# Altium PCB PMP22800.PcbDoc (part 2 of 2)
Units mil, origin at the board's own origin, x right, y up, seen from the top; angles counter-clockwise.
Board outline 4251.97 x 3450 mil, 2 copper layers (Top Layer, Bottom Layer), stack 62 mil thick; 97 components, 47 nets, 286 pads, 121 vias.
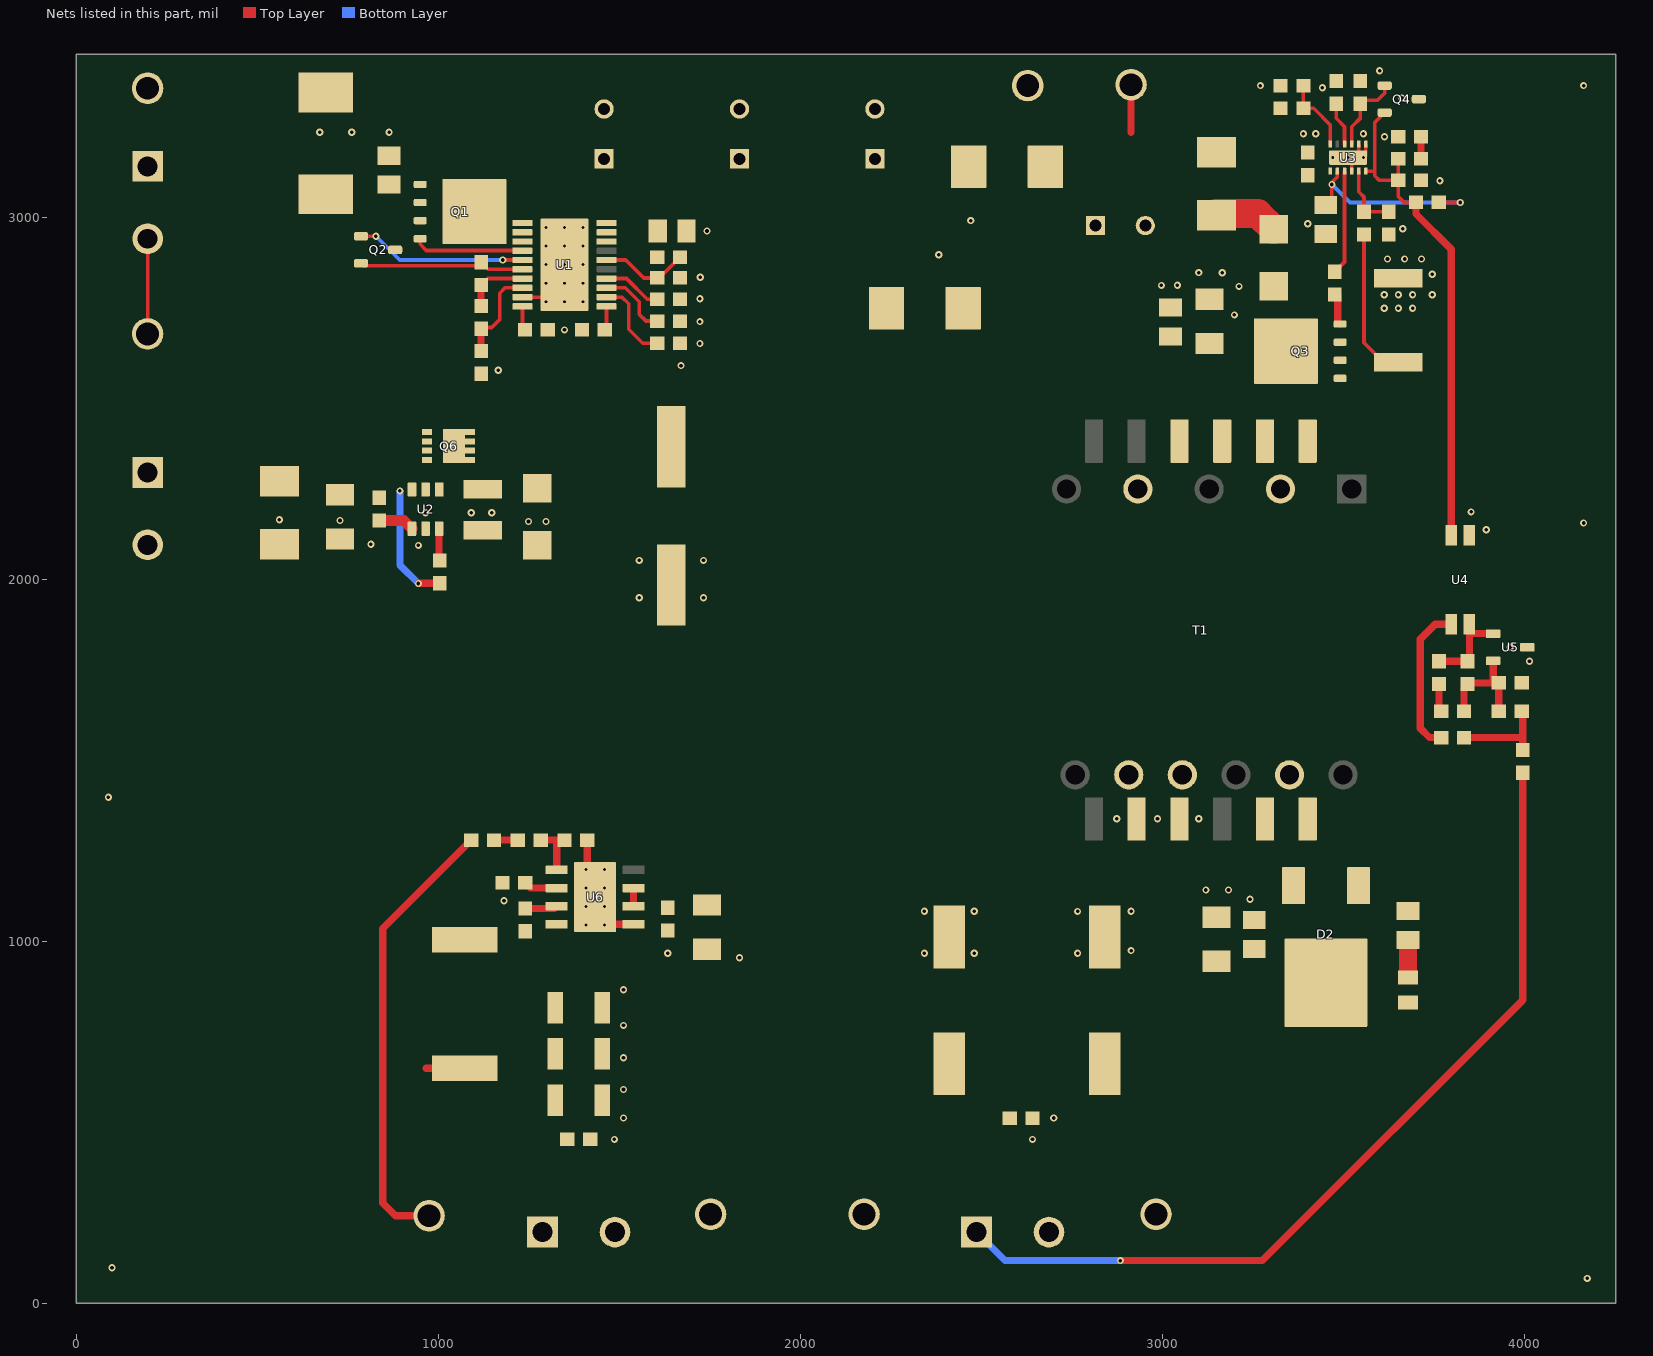
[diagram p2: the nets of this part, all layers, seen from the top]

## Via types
v1: diameter 20, hole 10, Top Layer to Bottom Layer, 91 vias
v2: diameter 19.68, hole 7.87, Top Layer to Bottom Layer, 16 vias
v3: diameter 19.68, hole 7.87, Top Layer to Bottom Layer, tented both sides, 10 vias
v4: diameter 20, hole 10, Top Layer to Bottom Layer, tented top, 4 vias

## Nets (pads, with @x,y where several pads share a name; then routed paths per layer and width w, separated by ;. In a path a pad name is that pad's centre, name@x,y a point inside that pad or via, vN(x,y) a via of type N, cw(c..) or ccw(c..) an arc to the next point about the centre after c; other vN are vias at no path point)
COMP: C22.1 C23.1 Q4.2 R14.2 U3.6 U4.4 | length 1400.3
  Top Layer w10: U3.6@3562.1,3127.27 3586.02,3127.27 ; Q4.2@3613.87,3288.88 3586.71,3261.72 3586.71,3127.27 ; C22.1@3651.28,3161.72 C23.1@3651.28,3102.66 ; R14.2@3700.49,3040.88 3667.86,3040.88 3651.28,3057.46 C23.1@3651.28,3102.66 ; 3586.02,3127.27 3586.71,3127.27 ; 3586.02,3127.27 3586.71,3126.58 ; 3586.71,3126.58 3586.71,3127.27 ; 3586.71,3126.58 3586.71,3114.37 3598.42,3102.66 C23.1@3651.28,3102.66
  Top Layer w20: R14.2@3700.49,3040.88 3700.49,3009.05 3798.03,2911.51 U4.4@3798.03,2122.05
IN_SYS: C5.1 D1.2 J1.2 Q1.1 Q1.2 Q1.3 Q2.2 R2.2 TP1.1 U1.6 | length 737.8
  Top Layer w10: J1.2@187.01,2930.76 J1.2@196.85,2940.61 TP1.1@196.85,2677.86 ; Q2.2@786.12,2872.7 792.95,2865.88 1108.27,2865.88 R2.2@1118.11,2875.72 1137.6,2856.23 U1.6@1232.28,2856.23
NetC1_1: C1.1 C2.1 C3.1 C4.1 J4.1 R1.2 U1.18 U1.19 U1.20
NetC6_1: C6.1 U1.10 | length 67.9
  Top Layer w10: U1.10@1232.28,2753.87 1232.28,2695.81 C6.1@1239.26,2688.83
NetC7_1: C7.1 R9.1 | length 95.3
  Top Layer w50: R9.1@3678.15,908.05 C7.1@3678.15,1003.31
NetC7_2: C7.2 D2.1 D2.3 pad.10 T1.11 T1.12
NetC18_1: C18.1 R17.1 R18.1 R21.2 U5.2 | length 307.5
  Top Layer w20: R18.1@3832.87,1634.84 3832.87,1700.79 C18.1@3842.72,1710.63 3845.67,1713.58 R21.2@3913.58,1713.58 ; U5.2@3913.58,1774.61 R21.2@3913.58,1713.58 ; R17.1@3929.33,1634.84 R21.2@3929.33,1713.58 R21.2@3913.58,1713.58
NetC18_2: C18.2 C20.2 U4.2 U5.1 | length 253.1
  Top Layer w20: C20.2@3763.98,1773.62 C18.2@3842.72,1773.62 3848.03,1778.94 U4.2@3848.03,1860.63 ; U4.2@3848.03,1875.98 U4.2@3848.03,1860.63 ; U5.1@3913.58,1850.39 3858.27,1850.39 U4.2@3848.03,1860.63
NetC19_2: C19.2 R15.1 U3.5 | length 194.8
  Top Layer w10: U3.5@3542.42,3127.27 3542.42,3070.11 3556.79,3055.74 R15.1@3556.79,3015.19 C19.2@3633.56,3015.19
NetC20_1: C20.1 R18.2 | length 78.2
  Top Layer w20: C20.1@3763.98,1710.63 3763.98,1640.75 R18.2@3769.88,1634.84
NetC22_2: C22.2 R22.2 | length 60.9
  Top Layer w20: C22.2@3714.27,3161.72 R22.2@3714.27,3222.6
NetC24_1: C24.1 U6.7 | length 89.3
  Top Layer w20: C24.1@1240.16,1090.55 1320.28,1090.55 U6.7@1326.77,1097.05
NetC24_2: C24.2 L1.1 U6.8
NetC27_1: C27.1 C28.1 C29.1 C30.2 J3.1 L1.2 R23.2 TP7.1 | length 1352.6
  Top Layer w20: 966.54,649.61 L1.2@1072.83,649.61 ; TP7.1@974.41,241.84 881.55,241.84 846.46,276.93 846.46,1035.24 R23.2@1090.75,1279.53
NetC31_1: C31.1 U6.6 | length 92.6
  Top Layer w20: C31.1@1240.16,1161.42 1254.53,1147.05 U6.6@1326.77,1147.05
NetC32_1: C32.1 C33.1 D6.1 J5.1 Q6.5 Q6.6 Q6.7 Q6.8 Q6.9 U2.4
NetC34_1: C34.1 C36.1 D7.2 J6.1 Q6.1 Q6.2 Q6.3 R27.2 U2.6 | length 337.1
  Top Layer w20: v1(944.88,1988.19) 945.87,1989.17 R27.2@1004.43,1989.17
  Bottom Layer w20: v1(893.7,2244.09) 893.7,2039.37 v1(944.88,1988.19)
NetC36_2: C36.2 U2.1 | length 99.9
  Top Layer w30: C36.2@836.61,2162.4 904.53,2162.4 U2.1@927.17,2139.76
NetD3_1: D3.1 D4.1 | length 177
  Top Layer w80: D3.1@3148.03,3009.86 3263.7,3009.86 D4.1@3307.09,2966.47
NetD4_2: D4.2 pad.2@3325.88,2249.19 Q3.5 Q3.6 Q3.7 Q3.8 Q3.9@3341.14,2629.92 T1.1 T1.2
NetQ1_4: Q1.4 Q2.3 U1.4 | length 305.8
  Top Layer w10: Q1.4@949.8,2940.61 949.8,2925.13 966.65,2908.28 1232.28,2908.28 U1.4@1232.28,2907.41
NetQ1_5: Q1.5 Q1.6 Q1.7 Q1.8 Q1.9@1099.41,3015.61 U1.1 U1.2 U1.3
NetQ2_1: Q2.1 U1.5 | length 473.4
  Top Layer w10: Q2.1@786.12,2947.51 v1(827.51,2947.51) ; v1(1177.95,2881.82) U1.5@1232.28,2881.82
  Bottom Layer w10: v1(827.51,2947.51) 893.19,2881.82 v1(1177.95,2881.82)
NetQ3_1: Q3.1 Q3.2 Q3.3 R15.2 R19.2 | length 416.7
  Top Layer w10: R15.2@3556.79,2952.2 3556.79,2652.94 R19.2@3610.58,2599.15
  Top Layer w20: R19.2@3610.58,2599.15 R19.2@3651.92,2599.15
NetQ3_4: Q3.4 R13.2 | length 84.1
  Top Layer w20: R13.2@3484.25,2786.35 3484.25,2711.42 Q3.4@3490.75,2704.92
NetQ6_4: Q6.4 U2.5
NetR1_1: R1.1 R3.2 U1.16 | length 247.4
  Top Layer w10: U1.16@1464.57,2881.82 1517.78,2881.82 1567.29,2832.32 R3.2@1604.59,2832.32 1610.04,2832.32 R1.1@1667.58,2889.86
NetR2_1: R2.1 R4.2 U1.7 | length 175.7
  Top Layer w10: R2.1@1118.11,2812.73 1136.02,2830.64 U1.7@1232.28,2830.64
  Top Layer w20: R4.2@1118.11,2758.6 R2.1@1118.11,2812.73
NetR4_1: R4.1 R7.2 U1.8 | length 257.1
  Top Layer w10: R4.1@1118.11,2695.6 1147.44,2695.6 1169.29,2717.46 1169.29,2790 1184.35,2805.05 U1.8@1232.28,2805.05
  Top Layer w20: R7.2@1118.11,2640.48 R4.1@1118.11,2695.6
NetR5_1: R5.1 U1.14 | length 163.8
  Top Layer w10: U1.14@1464.57,2830.64 1519.75,2830.64 1577.13,2773.26 R5.1@1604.59,2773.26
NetR6_1: R6.1 U1.11 | length 67
  Top Layer w10: R6.1@1459.74,2688.83 1464.57,2693.67 U1.11@1464.57,2753.87
NetR8_2: R8.2 U1.12 | length 233.7
  Top Layer w10: U1.12@1464.57,2779.46 1506.96,2779.46 1525.59,2760.83 1525.59,2690.95 1564.46,2652.08 R8.2@1604.59,2652.08
NetR10_1: R10.1 R11.2 U3.12 | length 209.1
  Top Layer w10: R11.2@3389.46,3363.68 R10.1@3389.46,3300.69 3418.01,3300.69 3463.68,3255.02 U3.12@3463.68,3202.07
NetR12_1: R12.1 R16.2 R17.2 | length 271.6
  Top Layer w20: R16.2@3833.07,1562.65 3990.69,1562.65 3995.28,1558.07 ; R17.2@3992.32,1634.84 3995.28,1631.89 3995.28,1558.07 ; R12.1@3995.28,1528.54 3995.28,1558.07
NetR13_1: R13.1 U3.3 | length 289.2
  Top Layer w10: R13.1@3475.92,2849.34 3503.05,2876.47 U3.3@3503.05,3127.27
NetR16_1: R16.1 U4.1 | length 417.9
  Top Layer w20: R16.1@3770.08,1562.65 3737.74,1562.65 3712.01,1588.39 3712.01,1834.25 3753.74,1875.98 U4.1@3798.03,1875.98
NetR20_2: R20.2 U3.10 | length 121
  Top Layer w10: R20.2@3479.79,3313.49 3479.79,3273.43 3503.05,3250.17 U3.10@3503.05,3202.07
NetR23_1: R23.1 R24.1 | length 65.7
  Top Layer w20: R23.1@1153.74,1279.53 R24.1@1219.49,1279.53
NetR24_2: R24.2 R25.2 U6.5 | length 126.8
  Top Layer w20: R24.2@1282.48,1279.53 1326.77,1279.53 U6.5@1326.77,1197.05
NetR26_2: R26.2 U1.13 | length 198.5
  Top Layer w10: U1.13@1464.57,2805.05 1516.51,2805.05 1555.12,2766.44 1555.12,2731.57 1573.39,2713.3 R26.2@1604.59,2713.3
NetR27_1: R27.1 U2.3 | length 88.6
  Top Layer w20: U2.3@1001.97,2139.76 1001.97,2054.63 R27.1@1004.43,2052.17
PGND: C1.2 C2.2 C3.2 C4.2 C5.2 C6.2 C8.2 C11.2 C12.2 C13.2 C17.1 C19.1 C21.2 C23.2 C32.2 C33.2 C34.2 D1.1 D6.2 D7.1 J1.1 J6.2 Q4.3 R3.1 R5.2 R6.2 R7.1 R8.1 R11.1 R19.1 R20.1 R22.1 R26.1 TP2.1 TP5.1 U1.9 U1.21 U2.2 U3.4 U3.7 U3.8 U3.13 U4.3 | length 245.9
  Top Layer w10: U1.9@1232.28,2779.46 1335.63,2779.46 v3(1348.43,2766.67) ; v2(3512.89,3164.67) 3522.73,3154.83 U3.4@3522.73,3127.27 ; U3.8@3542.42,3202.07 3542.42,3177.46 v2(3555.21,3164.67) 3562.1,3171.56 U3.7@3562.1,3202.07
  other v1: 1555.08,1948.82 1732.28,1948.82 1555.08,2052.17 1732.28,2052.17 944.88,2093.5 813.68,2097.05 3894.43,2136.81 4163.39,2155.51 1249.11,2159.45 1297.24,2159.45 728.35,2162.4 561.02,2164.37 964.57,2184.06 1090.84,2184.06 1147.44,2184.06 3852.56,2186.02 1165.39,2577.49 1670.08,2590.29 1722.44,2651.36 1722.44,2711.67 3198.82,2730.26 3612.55,2748.75 3651.92,2748.75 3690.94,2748.75 1722.44,2774.87 3612.55,2786.15 3651.92,2786.22 3690.94,2786.15 3745.22,2786.15 3211.6,2808.99 2997.28,2811.66 3041.34,2812.26 1723.25,2833.93 3745.22,2842.26 3100.39,2847.2 3165.33,2846.92 3621.75,2884.65 3668.99,2884.65 2381.89,2896.62 1742.13,2962.05 3401.38,2982.28 2470.47,2990.78 3766.43,3100.76 3389.46,3230.81 3423.38,3230.81 3555.21,3230.81 672.05,3234.64 761.01,3234.64 863.88,3234.64 3661.12,3329.24 3441.93,3357.78 3270.72,3363.68 4163.39,3363.68 3599.96,3404.97
  other v2: 1297.24,2817.85 1348.43,2817.85 1399.61,2817.85 1297.24,2869.03 1348.43,2869.03 1399.61,2869.03 1297.24,2920.21 1348.43,2920.21 1399.61,2920.21 3470.57,3164.67
  other v3: 1297.24,2766.67 1399.61,2766.67 1297.24,2971.39 1348.43,2971.39 1399.61,2971.39
  other v4: 1348.43,2688.83 3715.7,2884.65 3664.07,2967.95 3613.28,3222.6
SGND: C9.2 C10.2 C14.2 C15.2 C16.2 C25.2 C26.2 C27.2 C28.2 C29.2 C30.1 C31.2 J2.2 J3.2 pad.7 pad.8 R21.1 R25.1 T1.8 T1.9 TP6.1 TP8.1 U5.3 U6.1 U6.9 | length 163.8
  Top Layer w20: v3(1407.48,1198.82) 1411.42,1202.76 R25.1@1411.42,1279.53 ; v3(1458.66,1045.28) 1460.43,1047.05 U6.1@1539.37,1047.05
  other v1: 4173.23,68.9 98.43,98.43 1486.22,452.76 2641.17,452.76 1511.33,511.81 2699.67,511.81 1511.33,590.55 1511.33,678.15 1511.33,767.72 1511.33,866.14 1831.78,954.72 1633.86,967.32 2342.52,966.83 2480.32,967.32 2765.75,966.83 2913.39,974.41 2342.52,1083.31 2480.32,1083.31 2765.75,1082.68 2913.39,1083.31 1181.43,1112.2 3242,1116.14 3120.08,1141.73 3182.4,1141.73 2986.36,1338.19 2874.02,1338.58 3100.39,1338.58 88.58,1397.64 4013.98,1773.62 3960.83,1812.01
  other v2: 1407.48,1096.46 1458.66,1096.46 1407.48,1147.64 1458.66,1147.64
  other v3: 1407.48,1045.28 1458.66,1198.82
SS: C21.1 Q4.1 U3.9 | length 221.1
  Top Layer w10: U3.9@3522.73,3202.07 3522.73,3249.9 3546.94,3274.12 C21.1@3546.94,3313.49 3556.79,3323.33 3593.86,3323.33 3613.87,3343.35 Q4.1@3613.87,3363.68
VCC: C17.2 R14.1 U3.2 | length 549.6
  Top Layer w10: C17.2@3451.25,3033.54 C17.2@3468.2,3033.54 ; C17.2@3468.2,3034.86 v1(3468.2,3090.55) 3468.2,3096.91 3483.36,3112.07 U3.2@3483.36,3127.27 ; R14.1@3763.48,3040.88 v1(3822.53,3040.88)
  Bottom Layer w10: v1(3468.2,3090.55) 3517.88,3040.88 v1(3822.53,3040.88)
VIN_PRI: C8.1 C11.1 C12.1 C13.1 D3.2 J4.2 J5.2 pad.4 R10.2 T1.3 T1.4 TP3.1 U3.1 | length 131.5
  Top Layer w20: 2913.39,3234.64 TP3.1@2913.39,3366.14
VOUT_24V: C9.1 C10.1 C14.1 C15.1 C16.1 C25.1 C26.1 D2.2 J2.1 R9.2 R12.2 TP4.1 U6.2 U6.3 | length 2517.3
  Top Layer w20: U6.2@1539.37,1097.05 U6.3@1539.37,1147.05 ; v1(2883.86,118.11) 3275.87,118.11 3995.28,837.51 R12.2@3995.28,1465.55
  Bottom Layer w20: J2.1@2486.61,196.85 2565.35,118.11 v1(2883.86,118.11)
pads on no net: Q1.9@1044.88,2958.52 Q1.9@1044.88,3015.61 Q1.9@1044.88,3072.69 Q1.9@1081.49,3015.61 Q1.9@1114.96,2958.52 Q1.9@1114.96,3015.61 Q1.9@1114.96,3072.69 Q3.9@3325.59,2572.83 Q3.9@3325.59,2629.92 Q3.9@3325.59,2687.01 Q3.9@3359.05,2629.92 Q3.9@3395.67,2572.83 Q3.9@3395.67,2629.92 Q3.9@3395.67,2687.01 T1.5 T1.6 T1.7 T1.10 U1.15 U1.17 U3.11 U6.4

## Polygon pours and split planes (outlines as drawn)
VOUT_24V on Top Layer "TOP_LAYER_VOUT_24V_P004" (solid, remove dead copper, pour order 4): 2248.71,1023.62 2366.82,905.51 2883.12,905.51 3001.23,1023.62 3225.13,1023.62 3572.83,1023.62 3598.82,997.64 3598.82,879.53 3612.2,866.14 3710.63,866.14 3730.31,846.46 3730.31,748.03 3520.6,538.31 2608.27,538.31 2608.27,110.76 2556.57,59.06 2234.25,59.06 2007.87,285.43 2007.87,828.46 1770.58,1065.75 1515.75,1065.75 1505.91,1075.59 1505.91,1112.2 1574.8,1112.2 1620.67,1158.07 1909.45,1158.07 2114.26,1158.07
SGND on Top Layer "TOP_LAYER_SGND_P044" (solid, remove dead copper, pour order 44): 4226.48,1834.25 3186.07,1834.25 2808.51,1456.69 49.21,1456.69 19.68,1427.17 19.68,78.74 68.9,29.53 4202.76,29.53 4226.48,53.25
PGND on Top Layer "TOP_LAYER_PGND_P040" (solid, remove dead copper, pour order 40): 25.49,1874.12 49.21,1850.39 1978.35,1850.39 2225,2097.05 4199.31,2097.05 4232.28,2130.02 4232.28,3385.83 4192.91,3425.2 45.17,3425.2 25.49,3405.51
NetC27_1 on Top Layer "TOP_LAYER_NETC27_1_P036" (solid, remove dead copper, pour order 36): 1368.11,872.05 1120.08,872.05 895.67,647.64 895.67,529.53 895.67,45.9 912.04,29.53 1371.06,29.53 1387.8,46.26 1387.8,852.36
NetC7_2 on Top Layer "TOP_LAYER_NETC7_2_P034" (solid, remove dead copper, pour order 34): 3228.35,1397.64 3228.35,1518.87 3264.6,1555.12 3388,1555.12 3415.23,1527.89 3415.23,1437.01 3730.31,1121.92 3730.31,1061.61 3712.01,1043.31 3364.17,1043.31 3228.35,1179.13
NetQ3_1 on Top Layer "TOP_LAYER_NETQ3_1_P030" (solid, remove dead copper, pour order 30): 3513.78,2785.43
NetQ3_1 on Top Layer "TOP_LAYER_NETQ3_1_P002" (solid, remove dead copper, pour order 2): 3475.92,2673.95 3464.57,2662.6 3464.57,2542.13 3479.13,2527.56 3704.52,2527.56 3733.04,2556.08 3733.04,2619.02 3678.11,2673.95
NetD4_2 on Top Layer "TOP_LAYER_NETD4_2_P028" (solid, remove dead copper, pour order 28): 3238.19,2324.24 3238.19,2217.32 3271.46,2184.06 3411.75,2184.06 3441.93,2214.24 3441.93,2730.26 3378.41,2792.85 3378.41,2846.92 3356.3,2869.03 3257.87,2869.03 3238.19,2849.34
VIN_PRI on Top Layer "TOP_LAYER_VIN_PRI_P000" (solid, remove dead copper, pour order 0): 3465.24,3149.9 3380.31,3149.9 3360.92,3169.29 3361.46,3169.83 3361.46,3317.71 3351.78,3327.39 3283.64,3327.39 3243.65,3287.4 2687.01,3287.4 2605.98,3206.37 2605.98,3071.04 2497.54,2962.6 2353.46,2818.52 2353.46,2670.78 2455.35,2568.9 2741.93,2568.9 2841.05,2469.78 2841.05,2227.85 2884.84,2184.06 3115.01,2184.06 3200.79,2269.83 3200.79,2673.95 3169.82,2704.92 2993.9,2704.92 2913.39,2785.43 2913.39,3026.94 2957.49,3071.04 3358.64,3071.04 3425.2,3071.04 3474.96,3120.8 3474.96,3131.2 3470.52,3135.64 3470.56,3144.58
NetC24_2 on Top Layer "TOP_LAYER_NETC24_2_P026" (solid, remove dead copper, pour order 26): 1362.2,1062.99 976.38,1062.99 966.54,1053.15 966.54,962.6 974.41,954.72 1171.26,954.72 1214.57,998.03 1269.68,998.03 1301.18,1029.53 1361.22,1029.53 1368.11,1036.42 1368.11,1057.09
NetC32_1 on Top Layer "TOP_LAYER_NETC32_1_P008" (solid, remove dead copper, pour order 8): 1781.5,2208.76 1889.01,2208.76 2335.99,2655.75 2335.99,2827.33 2321.89,2841.43 2122.93,2841.43 1781.5,2500 1055.3,2500 990.93,2435.63 990.93,2222.27 1004.43,2208.76
NetQ6_4 on Top Layer "TOP_LAYER_NETQ6_4_P024" (solid, remove dead copper, pour order 24): 949.6,2227.9 981.1,2227.9 981.1,2342.52 949.6,2342.52
NetC34_1 on Top Layer "TOP_LAYER_NETC34_1_P022" (solid, remove dead copper, pour order 22): 20.67,2213.58 20.67,2451.77 34.18,2465.28 982.84,2465.28 997.34,2450.79 997.34,2342.52 941.73,2342.52 941.73,2228.35 907.28,2193.9 40.35,2193.9
NetC1_1 on Top Layer "TOP_LAYER_NETC1_1_P006" (solid, remove dead copper, pour order 6): 2519.68,3021.65 2551.97,3021.65 2588.58,3058.27 2588.58,3197.75 2551.69,3238.19 2401.57,3238.19 1440.56,3238.19 1417.32,3214.95 1417.32,2941.21 1434.43,2924.11 1518.29,2924.11 1578.23,2864.17 1633.86,2864.17 1633.86,2994.16 1661.35,3021.65
NetQ1_4 on Top Layer "TOP_LAYER_NETQ1_4_P020" (solid, remove dead copper, pour order 20): 972.44,2952.76 882.58,2952.76 853.05,2923.23 853.05,2890.42 860.93,2882.55 961.31,2882.55 975.89,2897.13 975.89,2949.31
NetQ1_5 on Top Layer "TOP_LAYER_NETQ1_5_P012" (solid, remove dead copper, pour order 12): 1011.81,3129.92 997.34,3115.45 997.34,2938.36 1013.78,2921.91 1268.37,2921.91 1269.68,2923.23 1269.68,3120.08 1259.84,3129.92
IN_SYS on Top Layer "TOP_LAYER_IN_SYS_P010" (solid, remove dead copper, pour order 10): 167.32,2830.64 80.04,2830.64 62.72,2847.96 62.72,3045 73.64,3055.92 255.91,3055.92 329.9,3129.92 334.65,3129.92 969.15,3129.92 984.25,3114.82 984.25,2986.02 967.39,2969.16 764.43,2969.16 748.03,2952.76 748.03,2910.1 761.01,2897.13 803.66,2897.13 825.33,2875.46 823.88,2874.02 823.88,2849.34 805.18,2830.64 787.4,2830.64
SGND on Bottom Layer "BOTTOM_LAYER_SGND_P042" (solid, remove dead copper, pour order 42): 4232.28,1834.25 3185.76,1834.25 2808.2,1456.69 49.21,1456.69 19.68,1427.17 19.68,78.74 68.9,29.53 4202.76,29.53 4232.28,59.06
PGND on Bottom Layer "BOTTOM_LAYER_PGND_P038" (solid, remove dead copper, pour order 38): 25.49,1874.12 49.21,1850.39 1978.35,1850.39 2225,2097.05 4198.43,2097.05 4232.28,2130.91 4232.28,3385.83 4192.91,3425.2 45.17,3425.2 25.49,3405.51

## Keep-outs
Keep-Out Layer:
  text ".Layer_Name" at 577,-858.49 h60

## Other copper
Top Layer:
  text ".Layer_Name" at 577,-858.49 h60
Bottom Layer:
  text ".Layer_Name" at 577,-858.49 h60

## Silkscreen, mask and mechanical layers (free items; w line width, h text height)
Top Overlay:
  text "'.PRJ_Number'.PCB_Rev" at 167.32,59.06 h108.27
  text ".Layer_Name" at 577,-858.49 h60
Bottom Overlay:
  text ".Layer_Name" at 577,-858.49 h60
Top Paste:
  text ".Layer_Name" at 577,-858.49 h60
Bottom Paste:
  text ".Layer_Name" at 577,-858.49 h60
Top Solder:
  text ".Layer_Name" at 577,-858.49 h60
  text ".Layer_Name" at 577,-858.49 h60
Bottom Solder:
  text ".Layer_Name" at 577,-858.49 h60
Drill Guide:
  text ".Layer_Name" at 577,-858.49 h60
M1 Board Outline:
  the board outline again, w10
  text ".Layer_Name" at 577,-858.49 h60
M2 Board Dimensions:
  rectangle: 0,-275 125,-150
  rectangle: 125,-400 500,-275
  lines w7: 0,-275 1000,-275 ; 125,-400 125,-150 ; 250,-400 250,-150 ; 500,-400 500,-150 ; 750,-400 750,-150 ; 0,-400 1000,-400 1000,-150 0,-150 0,-400
  text ".Layer_Name" at 577,-858.49 h60
M3 3D STEP Top:
  text ".Layer_Name" at 577,-858.49 h60
M4 3D STEP Bottom:
  text ".Layer_Name" at 577,-858.49 h60
M5 Assembly Top:
  lines w10: -292,-930.17 6308,-930.17 ; -292,-726.83 6310,-726.83 ; -292,-523.5 -292,-1133.5 3713,-1133.5 6310,-1133.5 6310,-523.5 -291.5,-523.5 -291.5,-1133.5 1284,-1133.5 ; 2173,-1133.5 2173,-523.5 ; 3440,-726.83 3440,-523.5 ; 4280,-726.83 4280,-523.5 ; 4902,-1140 4902,-937.17
  text "COMPONENTS MARKED 'DNP' SHOULD NOT BE POPULATED." at 1153.5,-318.5 h60
  text "ASSEMBLY VARIANT:" at 1153,-434 h60
  text ".VariantName" at 2189,-434 h60
  text "PCB VIEWED FROM TOP SIDE" at -228.5,-655.67 h60
  text "BOARD #:" at 2248,-655.67 h60
  text ".PRJ_Number" at 2793.5,-655.67 h60
  text "REV:" at 3638,-655.67 h60
  text ".PCB_Rev" at 3929.5,-655.67 h60
  text "SVN REV:" at 4476,-655.67 h60
  text ".VersionControl_RevNumber" at 4982,-655.67 h60
  text "TID #:" at 2248,-859 h60
  text ".TID" at 2793.5,-859 h60
  text "PLOT NAME =" at -228.5,-1064.34 h60
  text ".plot_File_Name" at 577,-1064.34 h60
  text "GENERATED    :" at 2250,-1064.34 h60
  text ".Print_Date" at 3119.5,-1064.34 h60
  text ".Print_Time" at 3848.5,-1064.34 h60
  text "TEXAS INSTRUMENTS" at 5113,-1064.34 h60
M6 Assembly Bottom:
  lines w10: -292.5,-727.33 6309.5,-727.33 ; -290.5,-930.67 6309.5,-930.67 ; 1115.5,-1140.5 1115.5,-937.67 ; 1737.5,-727.33 1737.5,-524 ; 2577.5,-727.33 2577.5,-524 ; 3844.5,-1134 3844.5,-524 ; 4733.5,-1134 6309,-1134 6309,-524 -292.5,-524 -292.5,-1134 2304.5,-1134 6309.5,-1134 6309.5,-524
  text "COMPONENTS MARKED 'DNP' SHOULD NOT BE POPULATED." at 6102,-318 h60
  text ".VariantName" at 5058,-434 h60
  text "ASSEMBLY VARIANT:" at 6097,-434 h60
  text ".VersionControl_RevNumber" at 1035.5,-656.17 h60
  text "SVN REV:" at 1541.5,-656.17 h60
  text ".PCB_Rev" at 2088,-656.17 h60
  text "REV:" at 2379.5,-656.17 h60
  text ".PRJ_Number" at 3224,-656.17 h60
  text "BOARD #:" at 3769.5,-656.17 h60
  text "PCB VIEWED FROM BOTTOM SIDE" at 6246,-656.17 h60
  text ".TID" at 3224,-859.5 h60
  text "TID #:" at 3769.5,-859.5 h60
  text "TEXAS INSTRUMENTS" at 904.5,-1064.84 h60
  text ".Print_Time" at 2169,-1064.84 h60
  text ".Print_Date" at 2898,-1064.84 h60
  text "GENERATED    :" at 3767.5,-1064.84 h60
  text ".plot_File_Name" at 5440.5,-1064.84 h60
  text "PLOT NAME =" at 6246,-1064.84 h60
M9 Title Sheet:
  drawing of 57 lines, arcs and shapes, not listed
  text "1" at 739.84,8036.5 h70
  text "2" at 3235.5,8036.5 h70
  text "3" at 5724.84,8036.5 h70
  text "4" at 8231.51,8036.5 h70
  text "5" at 10730.5,8036.5 h70
  text "6" at 13235.5,8036.5 h70
  text "A" at -416.5,6893.5 h70
  text "A" at 14383.5,6893.5 h70
  text "B" at -416.5,4513.5 h70
  text "B" at 14383.5,4513.5 h70
  text "C" at -416.5,2138.5 h70
  text "C" at 14383.5,2138.5 h70
  text "PROJECT TITLE:" at 11343.5,277.5 h45
  text ".PRJ_Title" at 11393.5,144.17 h70
  text "DESIGNED FOR:" at 11343.5,-23.5 h45
  text ".PRJ_Customer" at 11393.5,-163.5 h70
  text "D" at -416.5,-231.5 h70
  text "D" at 14383.5,-231.5 h70
  text "FILE NAME:" at 11343.5,-323.5 h45
  text ".PCB_File_Name_No_Path" at 11393.5,-443.5 h70
  text "Texas Instruments (TI) and/or its licensors do not warrant the accuracy or completeness of this specification" at 6374,-605.34 h45
  text "ENGINEER:" at 11343.5,-613.5 h45
  text "LAYOUT BY:" at 12848.5,-613.5 h45
  text "or any information contained therein. TI and/or its licensors do not warrant that this design will meet" at 6329.01,-718 h45
  text ".PRJ_Engineer" at 11393.5,-768.49 h70
  text ".PCB_Layout" at 12899,-768.49 h70
  text "the specifications, will be suitable for your application or fit for any particular purpose, or will operate in" at 6329.01,-830.67 h45
  text ".Layer_Name" at 577,-858.49 h60
  text "ALTIUM DESIGNER VERSION:" at 12848.5,-923.5 h45
  text "an implementation. TI and/or its licensors do not warrant that the design is production worthy. You should" at 6329.01,-943.33 h45
  text "completely validate and test your design implementation to confirm the system functionality for your application." at 6374,-1056 h45
  text ".print_Scale" at 11393.5,-1056.83 h70
  text ".Application_BuildNumber" at 12899,-1056.83 h70
  text "1" at 739.84,-1263.5 h70
  text "2" at 3235.5,-1263.5 h70
  text "3" at 5724.84,-1263.5 h70
  text "4" at 8231.51,-1263.5 h70
  text "5" at 10730.5,-1263.5 h70
  text "6" at 13235.5,-1263.5 h70
M10 Fab Notes:
  drawing of 189 lines, arcs and shapes, not listed
  text "DESIGN INFORMATION" at 12382.02,6356.17 h60
  text "MIN. TRACK WIDTH:" at 11737.46,6224.05 h60
  text "8" at 12833.7,6224.05 h60
  text "MIL" at 12988.46,6224.05 h60
  text "MIN. CLEARANCE:" at 11737.46,6099.92 h60
  text "0.2" at 12773.7,6099.93 h60
  text "mm" at 12988.46,6099.92 h60
  text "MIN. VIA PAD SIZE:" at 11737.46,5975.8 h60
  text "24" at 12803.71,5975.8 h60
  text "MIL" at 12988.46,5975.8 h60
  text "0.05mm (2MIL)" at 12432.46,5845.9 h60
  text "MINIMUM ANNULAR RING" at 11408.23,5837.67 h60
  text "EXTERNAL" at 13140.46,5837.67 h60
  text "PER" at 11608.23,5727.55 h60
  text "IPC-D-275 CLASS 2 LEVEL C" at 11828.23,5727.54 h60
  text "MIL, HOLES" at 13316.46,5627.07 h60
  text "+/-" at 12924,5618.48 h60
  text "+/-" at 13778,5618.48 h60
  text "REGISTRATION TOLERANCES:" at 11408.23,5617.42 h60
  text "METAL" at 12608,5617.42 h60
  text "5" at 13184.2,5617.42 h60
  text "3" at 14017.2,5617.42 h60
  text "MIL" at 14133.46,5617.42 h60
  text "HOLE SIZE TOLERANCE (UNLESS OTHERWISE SPECIFIED):" at 11408.23,5519.1 h60
  text "+/-" at 13778,5516.23 h60
  text "3" at 14017.2,5515.17 h60
  text "MIL" at 14133.46,5515.17 h60
  text "MATERIAL:" at 11333.46,5377.52 h60
  text "FR-4 High Tg" at 12319.9,5249 h60
  text "X" at 12175.46,5241.01 h60
  text "FR-408" at 11754.46,5236.49 h60
  text "OTHER" at 13242.46,5236.49 h60
  text "62 MIL (1.6mm) +/-10%" at 12074.56,5093.46 h60
  text "X" at 11954.46,5091.01 h60
  text "THICKNESS:" at 11408.23,5085.24 h60
  text "OTHER" at 13359.46,5085.24 h60
  text "TOLERANCE:" at 11408.23,4946.92 h60
  text "X" at 12256.46,4946.92 h60
  text "ANSI IPC-6012 TYPE 3 CLASS 2" at 12434.48,4946.92 h60
  text "OTHER +/-" at 12434.46,4802.73 h60
  text "BOW & TWIST:" at 11408.23,4657.54 h60
  text "X" at 12256.46,4657.54 h60
  text "ANSI IPC-6012 TYPE 3 CLASS 2" at 12434.48,4657.54 h60
  text "OTHER +/-" at 12434.46,4510.85 h60
  text "DRILLING:" at 11333.46,4380.23 h60
  text "NC_DRILL FILES" at 13094.46,4275.04 h60
  text "REFERENCE:" at 11408.23,4271.1 h60
  text "X" at 12065.46,4271.01 h60
  text "AS SHOWN" at 12243.46,4271.1 h60
  text "X" at 12966.46,4271.1 h60
  text "OTHER" at 13392.46,4128.85 h60
  text "PTH COPPER THICKNESS:" at 11407.91,4125.32 h60
  text "X" at 12547.14,4125.32 h60
  text "20-30 um" at 12675.14,4125.32 h60
  text "BOARD FINISH:" at 11333.46,3977.73 h60
  text "SILKSCREEN:" at 11488.68,3867.6 h60
  text "X" at 12446.46,3867.6 h60
  text "TOP" at 12563.46,3867.6 h60
  text "X" at 12956.46,3867.6 h60
  text "BOTTOM" at 13074.46,3867.6 h60
  text "SILKSCREEN COLOR:" at 11488.68,3712.41 h60
  text "X" at 12445.46,3712.41 h60
  text "WHITE" at 12563.46,3712.41 h60
  text "OTHER" at 13074.46,3712.41 h60
  text "X" at 12576.46,3568.96 h60
  text "GREEN" at 12694.46,3568.96 h60
  text "OTHER" at 13312.46,3568.96 h60
  text "SOLDER RESIST COLOR:" at 11488.68,3562.1 h60
  text "X" at 12576.46,3414.71 h60
  text "MATTE" at 12694.46,3414.71 h60
  text "SEMI-GLOSS" at 13312,3414.07 h60
  text "IMMERSION GOLD (ENIG)" at 12394.46,3241.94 h60
  text "ENEPIG" at 13732,3234.72 h60
  text "SURFACE FINISH:" at 11333.46,3233.72 h60
  text "X" at 12216.46,3233.72 h60
  text "IMM. TIN/SILVER OR EQUIV" at 11663,3096.4 h60
  text "OTHER" at 13094.46,3092.47 h60
  text "ARRAY/PANEL:" at 11333.46,2937.09 h60
  text "CUT AND TRIM PER M1 BOARD OUTLINE" at 12394.46,2928.87 h60
  text "N.C. ROUTE" at 12394.46,2792.9 h60
  text "X" at 13082.46,2792.9 h60
  text "V. SCORE" at 13260.46,2792.9 h60
  text "CERTIFICATION:" at 11333.46,2663.77 h60
  text "MATERIALS AND WORKMANSHIP FOR ALL PCBS" at 12058.46,2663.77 h60
  text "TO MEET OR EXCEED THE REQUIREMENTS OF:" at 12058.46,2569.71 h60
  text "X" at 11695.97,2441.08 h60
  text "ANSI IPC-A-600F CLASS ->" at 11823.96,2441.08 h60
  text "X" at 13471.97,2441.08 h60
  text "2" at 13581.96,2441.08 h60
  text "1" at 13266.96,2439.58 h60
  text "3" at 13935.96,2439.58 h60
  text "X" at 12507.97,2293.39 h60
  text "RoHS" at 12635.96,2293.39 h60
  text "OTHER" at 13280.36,2293.39 h60
  text "PER ORDER" at 13677.42,2293.39 h60
  text "ALL BOARDS MUST MEET OR EXCEED UL94-V0 REQUIREMENTS." at 11361,2139.57 h60
  text "PCB MUST BEAR THE UL94V-0 UL REGISTERED MATERIAL ID NUMBER" at 11361,2023.5 h60
  text "ADDITIONAL REQUIREMENTS:" at 11333.46,1854.08 h60
  text "MICROSECTION:" at 11408.23,1746.95 h60
  text "YES" at 12313.96,1746.95 h60
  text "REQUIRED" at 13175.46,1602.62 h60
  text "BARE BOARD ELEC. TEST:" at 11408.23,1599.76 h60
  text "NONE" at 12713.96,1599.76 h60
  text "X" at 13057.46,1599.76 h60
  text "PER ORDER" at 13767.46,1599.76 h60
  text "XX MIL VIAS REQUIRE NON-CONDUCTIVE FILL AND PLANARIZE" at 11576.38,1394.82 h59
  text "XX MIL VIAS REQUIRE CONDUCTIVE FILL AND PLANARIZE" at 11584.38,1290.84 h60
  text "OUTER XX MIL TRACES REQUIRE 50 OHM SINGLE-ENDED IMPEDANCE" at 11583.39,1127.46 h58
  text "LAYER 2 & 3 (INNER LAYERS) XX MIL WIDE, XX MIL SPACE / TRACES REQUIRE 100 OHM DIFFERENTIAL IMPEDANCE" at 11575.39,891.74 h60
  text ".Layer_Name" at 577,-858.49 h60
M11 Gerber Information:
  lines w10: -292,-930.17 6308,-930.17 ; -292,-726.83 6310,-726.83 ; -292,-523.5 -292,-1133.5 3713,-1133.5 6310,-1133.5 6310,-523.5 -291.5,-523.5 -291.5,-1133.5 1284,-1133.5 ; 2173,-1133.5 2173,-523.5 ; 3440,-726.83 3440,-523.5 ; 4280,-726.83 4280,-523.5 ; 4902,-1140 4902,-937.17
  text "ALL ARTWORK VIEWED FROM TOP SIDE" at -228.5,-655.67 h60
  text "BOARD #:" at 2248,-655.67 h60
  text ".PRJ_Number" at 2793.5,-655.67 h60
  text "REV:" at 3638,-655.67 h60
  text ".PCB_Rev" at 3929.5,-655.67 h60
  text "SVN REV:" at 4476,-655.67 h60
  text ".VersionControl_RevNumber" at 4982,-655.67 h60
  text "LAYER NAME =" at -228.5,-858.49 h60
  text "TID #:" at 2248,-859 h60
  text ".TID" at 2793.5,-859 h60
  text "PLOT NAME =" at -228.5,-1064.34 h60
  text ".plot_File_Name" at 577,-1064.34 h60
  text "GENERATED    :" at 2250,-1064.34 h60
  text ".Print_Date" at 3119.5,-1064.34 h60
  text ".Print_Time" at 3848.5,-1064.34 h60
  text "TEXAS INSTRUMENTS" at 5113,-1064.34 h60
M12 Stackup:
  drawing of 191 lines, arcs and shapes, not listed
  text "Layer" at 9797.84,7560 h60
  text "Name" at 10207.76,7560 h60
  text "Material" at 11137.5,7560 h60
  text "Thickness" at 11997.27,7560 h60
  text "Constant" at 12647.1,7560 h60
  text "Board Layer Stack" at 13216.96,7560 h60
  text "1" at 9797.84,7440 h60
  text "Top Overlay" at 10207.76,7440 h60
  text "2" at 9797.84,7320 h60
  text "Top Solder" at 10207.76,7320 h60
  text "Solder Resist" at 11137.5,7320 h60
  text "0.40mil" at 11997.27,7320 h60
  text "3.5" at 12647.1,7320 h60
  text "3" at 9797.84,7200 h60
  text "Top Layer" at 10207.76,7200 h60
  text "Copper" at 11137.5,7200 h60
  text "1.40mil" at 11997.27,7200 h60
  text "4" at 9797.84,7080 h60
  text "Dielectric1" at 10207.76,7080 h60
  text "FR-4" at 11137.5,7080 h60
  text "59.20mil" at 11997.27,7080 h60
  text "4.8" at 12647.1,7080 h60
  text "5" at 9797.84,6960 h60
  text "Bottom Layer" at 10207.76,6960 h60
  text "Copper" at 11137.5,6960 h60
  text "1.40mil" at 11997.27,6960 h60
  text "6" at 9797.84,6840 h60
  text "Bottom Solder" at 10207.76,6840 h60
  text "Solder Resist" at 11137.5,6840 h60
  text "0.40mil" at 11997.27,6840 h60
  text "3.5" at 12647.1,6840 h60
  text "7" at 9797.84,6720 h60
  text "Bottom Overlay" at 10207.76,6720 h60
  text ".Layer_Name" at 577,-858.49 h60
M13 Component Bodies Top:
  text ".Layer_Name" at 577,-858.49 h60
M14 Component Bodies Bottom:
  text ".Layer_Name" at 577,-858.49 h60
M15 Courtyards Top:
  text ".Layer_Name" at 577,-858.49 h60
M16 Courtyards Bottom:
  text ".Layer_Name" at 577,-858.49 h60
Drill Drawing:
  circle w10: c7677.69,160.04 r27.63
  lines w10: 7650.07,-309.61 7705.32,-309.61 7677.69,-364.86 7650.07,-309.61 ; 7650.07,-226.73 7663.88,-226.73 7677.69,-240.54 7691.51,-226.73 7705.32,-226.73 7691.51,-212.92 7705.32,-199.1 7691.51,-199.1 7677.69,-185.29 7663.88,-199.1 7650.07,-199.1 7663.88,-212.92 7650.07,-226.73 ; 7650.07,-102.41 7663.88,-102.41 7663.88,-116.22 7691.51,-116.22 7691.51,-102.41 7705.32,-102.41 7705.32,-74.78 7691.51,-74.78 7691.51,-60.97 7663.88,-60.97 7663.88,-74.78 7650.07,-74.78 7650.07,-102.41 ; 7650.07,8.1 7705.32,8.1 7705.32,63.35 7650.07,63.35 7650.07,8.1 ; 7650.07,256.74 7677.69,270.55 7705.32,256.74 7691.51,284.36 7705.32,311.99 7677.69,298.18 7650.07,311.99 7663.88,284.36 7650.07,256.74
  lines w12: 7599.98,-402.16 10831.47,-402.16 ; 7599.98,343.76 10831.47,343.76 ; 7937.84,-526.48 7937.84,468.08 ; 8269.84,-526.48 8269.84,468.08 ; 8906.4,-526.48 8906.4,468.08 ; 9165.54,-526.48 9165.54,468.08 ; 9540.7,-526.48 9540.7,468.08 ; 10265.03,-526.48 10265.03,468.08 ; 7599.98,-526.48 10831.47,-526.48 10831.47,468.08 7599.98,468.08 7599.98,-526.48
  text "Symbol" at 7674.57,381.06 h72
  text "Quantity" at 7975.14,381.06 h72
  text "Finished Hole Size" at 8307.14,381.06 h72
  text "Plated" at 8943.7,381.06 h72
  text "Hole Type" at 9202.84,381.06 h72
  text "Drill Layer Pair" at 9578,381.06 h72
  text "Hole Tolerance" at 10302.33,381.06 h72
  text "26" at 7975.14,256.74 h60
  text "7.87mil (0.200mm)" at 8307.14,256.74 h60
  text "PTH" at 8943.7,256.74 h60
  text "Round" at 9202.84,256.74 h60
  text "Top Layer - Bottom Layer" at 9578,256.74 h60
  text "95" at 7975.14,132.42 h60
  text "10.00mil (0.254mm)" at 8307.14,132.42 h60
  text "PTH" at 8943.7,132.42 h60
  text "Round" at 9202.84,132.42 h60
  text "Top Layer - Bottom Layer" at 9578,132.42 h60
  text "8" at 7975.14,8.1 h60
  text "33.47mil (0.850mm)" at 8307.14,8.1 h60
  text "PTH" at 8943.7,8.1 h60
  text "Round" at 9202.84,8.1 h60
  text "Top Layer - Bottom Layer" at 9578,8.1 h60
  text "11" at 7975.14,-116.22 h60
  text "53.15mil (1.350mm)" at 8307.14,-116.22 h60
  text "PTH" at 8943.7,-116.22 h60
  text "Round" at 9202.84,-116.22 h60
  text "Top Layer - Bottom Layer" at 9578,-116.22 h60
  text "8" at 7975.14,-240.54 h60
  text "55.12mil (1.400mm)" at 8307.14,-240.54 h60
  text "PTH" at 8943.7,-240.54 h60
  text "Round" at 9202.84,-240.54 h60
  text "Top Layer - Bottom Layer" at 9578,-240.54 h60
  text "8" at 7975.14,-364.86 h60
  text "63.00mil (1.600mm)" at 8307.14,-364.86 h60
  text "PTH" at 8943.7,-364.86 h60
  text "Round" at 9202.84,-364.86 h60
  text "Top Layer - Bottom Layer" at 9578,-364.86 h60
  text "156 Total" at 7975.14,-489.18 h60
  text ".Layer_Name" at 577,-858.49 h60
M17 Embedded Cavity:
  text ".Layer_Name" at 577,-858.49 h60
M18 Embedded Assembly:
  text ".Layer_Name" at 577,-858.49 h60
M19 Embedded Keepout:
  text ".Layer_Name" at 577,-858.49 h60

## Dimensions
2735.33,2249.19 to 2758.95,1459.82 on M2 Board Dimensions
3499.11,1459.82 to 3522.73,2249.19 on M2 Board Dimensions
3203.05,1459.82 to 3351.08,1459.82 on M2 Board Dimensions
3055.01,1459.82 to 3203.05,1459.82 on M2 Board Dimensions
2906.98,1459.82 to 3055.01,1459.82 on M2 Board Dimensions
2758.95,1459.82 to 2906.98,1459.82 on M2 Board Dimensions
3325.88,2249.19 to 3522.73,2249.19 on M2 Board Dimensions
3129.03,2249.19 to 3325.88,2327.93 on M2 Board Dimensions
2932.18,2249.19 to 3129.03,2249.19 on M2 Board Dimensions
3351.08,1459.82 to 3499.11,1459.82 on M2 Board Dimensions
2735.33,2249.19 to 2758.95,1459.82 on M2 Board Dimensions
2932.18,2249.19 to 2735.33,2249.19 on M2 Board Dimensions
0,-400 to 1000,-400 on M2 Board Dimensions
0,0 to 0,3450 on M2 Board Dimensions
0,0 to 4251.97,0 on M2 Board Dimensions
